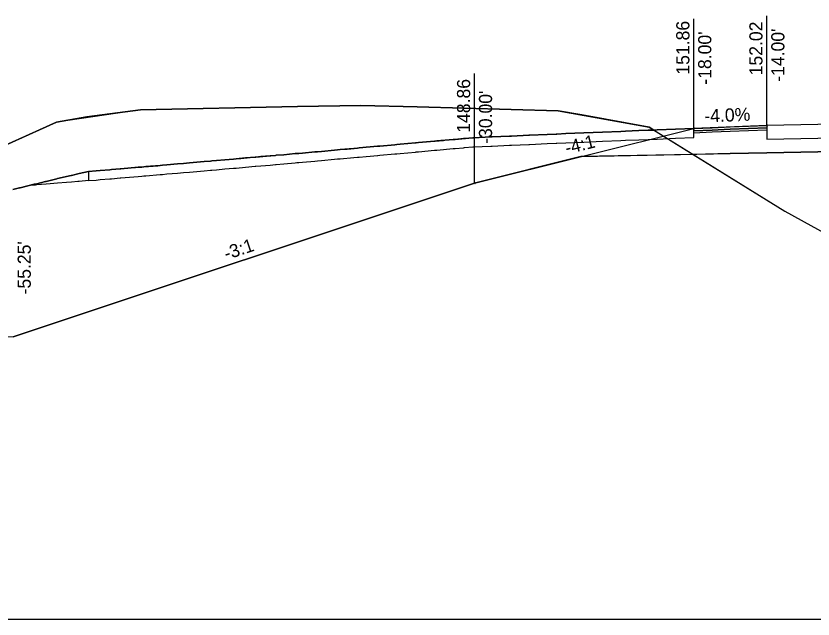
# Model space of a CAD drawing. Extents: x -26 to 4403, y -13 to 9578.
# Drawn here: x 3194.9 to 3238.53, y 8500 to 8533.02 of the extents above; entities that cross this region are included whole.
import ezdxf

# ---------------------------------------------------------------- set-up
doc = ezdxf.new("R2010")
doc.units = 0
for name, color, linetype in [('1', 7, 'Continuous'), ('CONST_LV3', 7, 'Continuous'), ('CONST_PROF_LV1', 7, 'Continuous'), ('Default', 7, 'Continuous'), ('DTM CONTOURS_MAJOR', 7, 'Continuous'), ('DTM_P_FINISHED_GRADE', 7, 'Continuous'), ('DTM_X_BOUNDARY', 7, 'Continuous'), ('DTM_X_GROUND', 7, 'Continuous'), ('XS_CELL', 7, 'Continuous'), ('XS_M_SHAPES_EARTHWORK', 7, 'Continuous'), ('XS_P_ASPHALT', 7, 'Continuous'), ('XS_P_DR_ASPHALT', 7, 'Continuous'), ('XS_P_DR_ASPHALT_B', 7, 'Continuous'), ('XS_P_DR_GRAVEL', 7, 'Continuous'), ('XS_P_GROUND', 7, 'Continuous'), ('XS_P_SHOULDER', 7, 'Continuous'), ('XS_P_SUBGRADE_GRANULAR', 7, 'Continuous'), ('XS_P_TX_CLEARZONE', 7, 'Continuous'), ('XS_P_TX_FS_BS', 7, 'Continuous')]:
    doc.layers.add(name, color=color, linetype=linetype)

msp = doc.modelspace()

# ---------------------------------------------------------------- linework, layer by layer
at = {"layer": '1'}
for p, q in [((3201.713, 8527.882), (3197.118, 8527.209)), ((3224.572, 8527.826), (3229.562, 8526.928))]:
    msp.add_line(p, q, dxfattribs=at)
at = {"layer": 'CONST_LV3'}
for points in [[(3198.868, 8524.501), (3199.286, 8524.536), (3199.509, 8524.555), (3200.037, 8524.599), (3200.124, 8524.607), (3200.607, 8524.647), (3200.649, 8524.651), (3200.714, 8524.657), (3201.69, 8524.738), (3201.788, 8524.748), (3201.898, 8524.757), (3202.667, 8524.821), (3202.927, 8524.845), (3203.163, 8524.865), (3203.737, 8524.913), (3204.066, 8524.944), (3204.403, 8524.972), (3204.809, 8525.006), (3205.203, 8525.043), (3205.553, 8525.072), (3205.619, 8525.077), (3205.882, 8525.099), (3206.339, 8525.142), (3206.813, 8525.182), (3206.956, 8525.193), (3207.208, 8525.217), (3207.721, 8525.26), (3207.987, 8525.285), (3208.031, 8525.288), (3208.605, 8525.342), (3209.105, 8525.384), (3209.143, 8525.387), (3209.56, 8525.421), (3210.18, 8525.479), (3210.28, 8525.487), (3210.388, 8525.496), (3210.587, 8525.513), (3211.254, 8525.575), (3211.402, 8525.587), (3211.616, 8525.605), (3212.327, 8525.671), (3212.508, 8525.686), (3212.646, 8525.697), (3213.015, 8525.732), (3213.224, 8525.749), (3213.6, 8525.784), (3213.677, 8525.79), (3214.468, 8525.863), (3214.68, 8525.88), (3214.709, 8525.883), (3214.823, 8525.892), (3215.64, 8525.967), (3215.741, 8525.976), (3215.748, 8525.976), (3215.934, 8525.991), (3216.773, 8526.068), (3216.806, 8526.071), (3216.936, 8526.081), (3217.804, 8526.161), (3217.854, 8526.165), (3218.302, 8526.206), (3218.382, 8526.212), (3218.835, 8526.253), (3218.893, 8526.258), (3218.945, 8526.262), (3219.864, 8526.345), (3219.908, 8526.349), (3219.924, 8526.35), (3219.952, 8526.351), (3220.891, 8526.394), (3220.949, 8526.397), (3220.959, 8526.397), (3221.917, 8526.44), (3221.967, 8526.442), (3222.016, 8526.444), (3222.975, 8526.487), (3222.981, 8526.487), (3223.469, 8526.508), (3223.491, 8526.509), (3223.98, 8526.53), (3224.974, 8526.573), (3224.996, 8526.574), (3225.991, 8526.616), (3226.995, 8526.657), (3226.998, 8526.657), (3228, 8526.698), (3228.259, 8526.708), (3229, 8526.738), (3230, 8526.778), (3231, 8526.818), (3232, 8526.858), (3233, 8526.898), (3234, 8526.938), (3235, 8526.978), (3236, 8527.018)], [(3220, 8523.858), (3220, 8523.858), (3225.826, 8525.314)]]:
    msp.add_lwpolyline(points, dxfattribs=at)
at = {"layer": 'DTM_P_FINISHED_GRADE'}
for points in [[(3198.868, 8524.501), (3199.286, 8524.536), (3199.509, 8524.555), (3200.037, 8524.599), (3200.124, 8524.607), (3200.607, 8524.647), (3200.649, 8524.651), (3201.598, 8524.73), (3201.788, 8524.748), (3201.898, 8524.757), (3202.006, 8524.767), (3202.793, 8524.833), (3202.927, 8524.845), (3203.163, 8524.865), (3203.737, 8524.913), (3204.066, 8524.944), (3204.403, 8524.972), (3204.809, 8525.006), (3205.203, 8525.043), (3205.553, 8525.072), (3205.619, 8525.077), (3205.882, 8525.099), (3206.339, 8525.142), (3206.813, 8525.182), (3206.956, 8525.193), (3207.473, 8525.242), (3207.987, 8525.285), (3208.031, 8525.288), (3208.311, 8525.315), (3208.813, 8525.356), (3209.105, 8525.384), (3209.143, 8525.387), (3209.56, 8525.421), (3210.18, 8525.479), (3210.28, 8525.487), (3210.388, 8525.496), (3210.587, 8525.513), (3211.254, 8525.575), (3211.402, 8525.587), (3211.616, 8525.605), (3212.327, 8525.671), (3212.508, 8525.686), (3212.646, 8525.697), (3213.398, 8525.767), (3213.6, 8525.784), (3213.677, 8525.79), (3214.065, 8525.826), (3214.286, 8525.844), (3214.68, 8525.88), (3214.709, 8525.883), (3214.823, 8525.892), (3215.639, 8525.967), (3215.741, 8525.976), (3215.748, 8525.976), (3215.934, 8525.991), (3216.773, 8526.068), (3216.806, 8526.071), (3216.936, 8526.081), (3217.804, 8526.161), (3217.854, 8526.165), (3217.94, 8526.172), (3218.835, 8526.253), (3218.893, 8526.258), (3218.945, 8526.262), (3219.4, 8526.303), (3219.449, 8526.307), (3219.908, 8526.349), (3219.924, 8526.35), (3219.952, 8526.351), (3220.891, 8526.394), (3220.949, 8526.397), (3220.959, 8526.397), (3221.917, 8526.44), (3221.967, 8526.442), (3222.016, 8526.444), (3222.975, 8526.487), (3222.981, 8526.487), (3223.007, 8526.488), (3223.98, 8526.53), (3224.475, 8526.552), (3224.503, 8526.553), (3224.996, 8526.574), (3225.991, 8526.616), (3226.995, 8526.657), (3226.998, 8526.657), (3228, 8526.698), (3228.001, 8526.698), (3228.259, 8526.708), (3229, 8526.738), (3230, 8526.778), (3231, 8526.818), (3232, 8526.858)], [(3232, 8526.858), (3233, 8526.898), (3234, 8526.938), (3235, 8526.978), (3236, 8527.018)]]:
    msp.add_lwpolyline(points, dxfattribs=at)
at = {"layer": 'DTM_X_GROUND'}
msp.add_lwpolyline([(3153.808, 8513.95), (3170.909, 8514.966), (3177.153, 8518.209), (3197.118, 8527.209), (3198.789, 8527.5), (3201.713, 8527.882), (3210.312, 8528.066), (3213.777, 8528.123), (3216.864, 8528.039), (3224.572, 8527.826), (3225.877, 8527.605), (3229.562, 8526.928), (3236.992, 8522.323), (3249.998, 8515.154), (3250, 8515.153), (3250.751, 8515.018), (3252.885, 8514.328), (3255.752, 8514.055), (3262.783, 8513.146), (3270.679, 8512.757), (3325.754, 8511.013), (3363.759, 8510.776), (3378.096, 8510.765), (3400, 8511.068)], dxfattribs=at)
at = {"layer": 'XS_CELL'}
msp.add_line((3000, 8500), (3250, 8500), dxfattribs=at)
at = {"layer": 'XS_M_SHAPES_EARTHWORK'}
for points in [[(3170.909, 8514.966), (3177.153, 8518.209), (3197.118, 8527.209), (3198.789, 8527.5), (3201.713, 8527.882), (3210.312, 8528.066), (3213.777, 8528.123), (3216.864, 8528.039), (3224.572, 8527.826), (3225.877, 8527.605), (3229.562, 8526.928), (3231.967, 8525.437), (3225.826, 8525.314), (3220, 8523.858), (3194.753, 8515.443)], [(3231.967, 8525.437), (3236.992, 8522.323), (3249.998, 8515.154), (3250, 8515.153), (3250.751, 8515.018), (3252.885, 8514.328), (3255.752, 8514.055), (3262.783, 8513.146), (3270.679, 8512.757), (3317.781, 8511.266), (3280, 8523.858), (3274.174, 8525.314), (3266, 8525.478), (3264, 8525.518), (3250, 8525.798), (3236, 8525.518), (3234, 8525.478)]]:
    msp.add_lwpolyline(points, close=True, dxfattribs=at)
at = {"layer": 'XS_P_ASPHALT'}
msp.add_lwpolyline([(3236, 8527.018), (3236, 8527.018), (3236, 8526.268), (3236, 8526.268), (3236, 8526.268), (3250, 8526.548), (3264, 8526.268), (3264, 8526.268), (3264, 8526.268), (3264, 8527.018), (3264, 8527.018), (3250, 8527.298), (3236, 8527.018)], dxfattribs=at)
at = {"layer": 'XS_P_DR_ASPHALT'}
msp.add_lwpolyline([(3233, 8526.898), (3234, 8526.938), (3234, 8526.938), (3234, 8526.938), (3235, 8526.978), (3235, 8526.978), (3235, 8526.978), (3235, 8526.978), (3236, 8527.018), (3236, 8526.893), (3235, 8526.853), (3235, 8526.853), (3235, 8526.853), (3235, 8526.853), (3234, 8526.813), (3234, 8526.813), (3234, 8526.813), (3233, 8526.773), (3233, 8526.773), (3233, 8526.773), (3232, 8526.733), (3232, 8526.858), (3233, 8526.898), (3233, 8526.898), (3233, 8526.898)], dxfattribs=at)
at = {"layer": 'XS_P_DR_ASPHALT_B'}
msp.add_lwpolyline([(3233, 8526.773), (3234, 8526.813), (3234, 8526.813), (3234, 8526.813), (3235, 8526.853), (3235, 8526.853), (3235, 8526.853), (3235, 8526.853), (3236, 8526.893), (3236, 8526.768), (3235, 8526.728), (3235, 8526.728), (3235, 8526.728), (3235, 8526.728), (3234, 8526.688), (3234, 8526.688), (3234, 8526.688), (3233, 8526.648), (3233, 8526.648), (3233, 8526.648), (3232, 8526.608), (3232, 8526.733), (3233, 8526.773), (3233, 8526.773), (3233, 8526.773)], dxfattribs=at)
at = {"layer": 'XS_P_DR_GRAVEL'}
for points in [[(3200.037, 8524.599), (3199.509, 8524.555), (3199.286, 8524.536), (3198.868, 8524.501), (3198.868, 8524.001), (3199.286, 8524.036), (3199.509, 8524.055), (3200.037, 8524.099), (3200.124, 8524.107), (3200.607, 8524.147), (3200.649, 8524.151), (3201.598, 8524.23), (3201.788, 8524.248), (3201.898, 8524.257), (3202.006, 8524.267), (3202.793, 8524.333), (3202.927, 8524.345), (3203.163, 8524.365), (3203.737, 8524.413), (3204.066, 8524.444), (3204.403, 8524.472), (3204.809, 8524.506), (3205.203, 8524.543), (3205.553, 8524.572), (3205.619, 8524.577), (3205.882, 8524.599), (3206.339, 8524.642), (3206.813, 8524.682), (3206.956, 8524.693), (3207.473, 8524.742), (3207.987, 8524.785), (3208.031, 8524.788), (3208.311, 8524.815), (3208.813, 8524.856), (3209.105, 8524.884), (3209.143, 8524.887), (3209.56, 8524.921), (3210.18, 8524.979), (3210.28, 8524.987), (3210.388, 8524.996), (3210.587, 8525.013), (3211.254, 8525.075), (3211.402, 8525.087), (3211.616, 8525.105), (3212.327, 8525.171), (3212.508, 8525.186), (3212.646, 8525.197), (3213.398, 8525.267), (3213.6, 8525.284), (3213.677, 8525.29), (3214.065, 8525.326), (3214.286, 8525.344), (3214.68, 8525.38), (3214.709, 8525.383), (3214.823, 8525.392), (3215.639, 8525.467), (3215.741, 8525.476), (3215.748, 8525.476), (3215.934, 8525.491), (3216.773, 8525.568), (3216.806, 8525.571), (3216.936, 8525.581), (3217.804, 8525.661), (3217.854, 8525.665), (3217.94, 8525.672), (3218.835, 8525.753), (3218.893, 8525.758), (3218.945, 8525.762), (3219.4, 8525.803), (3219.449, 8525.807), (3219.908, 8525.849), (3219.924, 8525.85), (3219.952, 8525.851), (3220.891, 8525.894), (3220.949, 8525.897), (3220.959, 8525.897), (3221.917, 8525.94), (3221.967, 8525.942), (3222.016, 8525.944), (3222.975, 8525.987), (3222.981, 8525.987), (3223.007, 8525.988), (3223.98, 8526.03), (3224.475, 8526.052), (3224.503, 8526.053), (3224.996, 8526.074), (3225.991, 8526.116), (3226.995, 8526.157), (3226.998, 8526.157), (3228, 8526.198), (3228.001, 8526.198), (3228.259, 8526.208), (3228.259, 8526.208), (3229, 8526.238), (3230, 8526.278), (3230, 8526.278), (3231, 8526.318), (3231, 8526.318), (3231, 8526.318), (3232, 8526.358), (3232, 8526.358), (3232, 8526.858), (3232, 8526.858), (3231, 8526.818), (3231, 8526.818), (3231, 8526.818), (3230, 8526.778), (3230, 8526.778), (3229, 8526.738), (3228.259, 8526.708), (3228.259, 8526.708), (3228.001, 8526.698), (3228, 8526.698), (3226.998, 8526.657), (3226.995, 8526.657), (3225.991, 8526.616), (3224.996, 8526.574), (3224.503, 8526.553), (3224.475, 8526.552), (3223.98, 8526.53), (3223.007, 8526.488), (3222.981, 8526.487), (3222.975, 8526.487), (3222.016, 8526.444), (3221.967, 8526.442), (3221.917, 8526.44), (3220.959, 8526.397), (3220.949, 8526.397), (3220.891, 8526.394), (3219.952, 8526.351), (3219.924, 8526.35), (3219.908, 8526.349), (3219.449, 8526.307), (3219.4, 8526.303), (3218.945, 8526.262), (3218.893, 8526.258), (3218.835, 8526.253), (3217.94, 8526.172), (3217.854, 8526.165), (3217.804, 8526.161), (3216.936, 8526.081), (3216.806, 8526.071), (3216.773, 8526.068), (3215.934, 8525.991), (3215.748, 8525.976), (3215.741, 8525.976), (3215.639, 8525.967), (3214.823, 8525.892), (3214.709, 8525.883), (3214.68, 8525.88), (3214.286, 8525.844), (3214.065, 8525.826), (3213.677, 8525.79), (3213.6, 8525.784), (3213.398, 8525.767), (3212.646, 8525.697), (3212.508, 8525.686), (3212.327, 8525.671), (3211.616, 8525.605), (3211.402, 8525.587), (3211.254, 8525.575), (3210.587, 8525.513), (3210.388, 8525.496), (3210.28, 8525.487), (3210.18, 8525.479), (3209.56, 8525.421), (3209.143, 8525.387), (3209.105, 8525.384), (3208.813, 8525.356), (3208.311, 8525.315), (3208.031, 8525.288), (3207.987, 8525.285), (3207.473, 8525.242), (3206.956, 8525.193), (3206.813, 8525.182), (3206.339, 8525.142), (3205.882, 8525.099), (3205.619, 8525.077), (3205.553, 8525.072), (3205.203, 8525.043), (3204.809, 8525.006), (3204.403, 8524.972), (3204.066, 8524.944), (3203.737, 8524.913), (3203.163, 8524.865), (3202.927, 8524.845), (3202.793, 8524.833), (3202.006, 8524.767), (3201.898, 8524.757), (3201.788, 8524.748), (3201.598, 8524.73), (3200.649, 8524.651), (3200.607, 8524.647), (3200.124, 8524.607), (3200.037, 8524.599)], [(3198.868, 8524.001), (3198.359, 8523.959), (3198.286, 8523.953), (3197.934, 8523.924), (3197.661, 8523.901), (3197.176, 8523.861), (3196.778, 8523.829), (3196.549, 8523.81), (3196.043, 8523.768), (3195.968, 8523.762), (3195.899, 8523.756), (3195.632, 8523.735)]]:
    msp.add_lwpolyline(points, dxfattribs=at)
at = {"layer": 'XS_P_GROUND'}
for p, q in [((3228, 8526.698), (3228.259, 8526.708)), ((3228.259, 8526.708), (3229, 8526.738)), ((3229, 8526.738), (3229.815, 8526.77)), ((3218.945, 8526.262), (3219.4, 8526.303)), ((3219.4, 8526.303), (3219.407, 8526.304)), ((3220.891, 8526.394), (3220.949, 8526.397)), ((3220.949, 8526.397), (3220.959, 8526.397)), ((3223.98, 8526.53), (3224.475, 8526.552)), ((3224.475, 8526.552), (3224.503, 8526.553)), ((3215.934, 8525.991), (3216.773, 8526.068)), ((3216.773, 8526.068), (3216.806, 8526.071)), ((3216.806, 8526.071), (3216.936, 8526.081)), ((3216.936, 8526.081), (3217.804, 8526.161)), ((3217.804, 8526.161), (3217.854, 8526.165)), ((3210.18, 8525.479), (3210.28, 8525.487)), ((3211.402, 8525.587), (3211.616, 8525.605)), ((3211.616, 8525.605), (3212.327, 8525.671)), ((3213.398, 8525.767), (3213.6, 8525.784)), ((3213.6, 8525.784), (3213.677, 8525.79)), ((3204.809, 8525.006), (3205.203, 8525.043)), ((3205.203, 8525.043), (3205.553, 8525.072)), ((3206.339, 8525.142), (3206.813, 8525.182)), ((3206.813, 8525.182), (3206.956, 8525.193)), ((3198.868, 8524.501), (3199.286, 8524.536)), ((3199.286, 8524.536), (3199.509, 8524.555)), ((3200.124, 8524.607), (3200.607, 8524.647)), ((3201.788, 8524.748), (3201.898, 8524.757)), ((3201.898, 8524.757), (3202.006, 8524.767)), ((3202.006, 8524.767), (3202.667, 8524.822)), ((3202.667, 8524.822), (3202.793, 8524.833)), ((3202.793, 8524.833), (3202.927, 8524.845)), ((3203.737, 8524.913), (3204.066, 8524.944))]:
    msp.add_line(p, q, dxfattribs=at)
for points in [[(3229.815, 8526.77), (3229.562, 8526.928), (3225.877, 8527.605), (3224.572, 8527.826), (3216.864, 8528.039), (3213.777, 8528.123), (3210.312, 8528.066), (3201.713, 8527.882), (3198.789, 8527.5), (3197.118, 8527.209), (3180.966, 8519.928)], [(3194.753, 8515.443), (3220, 8523.858), (3220, 8523.858), (3220, 8523.858), (3232, 8526.858)], [(3219.407, 8526.304), (3219.449, 8526.308), (3219.864, 8526.345), (3219.908, 8526.349)], [(3219.908, 8526.349), (3219.924, 8526.35), (3219.952, 8526.351), (3220.891, 8526.394)], [(3220.959, 8526.397), (3221.917, 8526.44), (3221.967, 8526.442)], [(3221.967, 8526.442), (3222.016, 8526.444), (3222.975, 8526.487)], [(3222.975, 8526.487), (3223.007, 8526.488), (3223.469, 8526.508), (3223.491, 8526.509), (3223.98, 8526.53)], [(3224.503, 8526.553), (3224.974, 8526.573), (3224.996, 8526.574), (3225.991, 8526.616)], [(3225.991, 8526.616), (3226.995, 8526.657), (3228, 8526.698)], [(3214.072, 8525.826), (3214.286, 8525.846), (3214.468, 8525.863), (3214.68, 8525.88), (3214.709, 8525.883), (3214.823, 8525.892), (3215.639, 8525.967)], [(3215.639, 8525.967), (3215.741, 8525.976), (3215.934, 8525.991)], [(3217.854, 8526.165), (3217.94, 8526.173), (3218.302, 8526.206), (3218.382, 8526.212), (3218.835, 8526.253)], [(3218.835, 8526.253), (3218.893, 8526.258), (3218.945, 8526.262)], [(3209.143, 8525.387), (3209.56, 8525.421), (3210.18, 8525.479)], [(3210.28, 8525.487), (3210.388, 8525.496), (3210.587, 8525.513), (3211.254, 8525.575), (3211.402, 8525.587)], [(3212.327, 8525.671), (3212.508, 8525.686), (3212.646, 8525.697)], [(3212.646, 8525.697), (3213.015, 8525.732), (3213.021, 8525.732)], [(3213.021, 8525.732), (3213.223, 8525.751), (3213.398, 8525.767)], [(3213.677, 8525.79), (3214.065, 8525.826), (3214.072, 8525.826)], [(3204.066, 8524.944), (3204.403, 8524.972), (3204.809, 8525.006)], [(3205.553, 8525.072), (3205.619, 8525.077), (3205.882, 8525.099), (3206.339, 8525.142)], [(3206.956, 8525.193), (3207.208, 8525.217), (3207.212, 8525.217)], [(3207.212, 8525.217), (3207.473, 8525.242), (3207.721, 8525.263)], [(3207.721, 8525.263), (3207.987, 8525.285), (3208.031, 8525.288), (3208.311, 8525.315), (3208.315, 8525.315)], [(3208.315, 8525.315), (3208.605, 8525.342), (3208.813, 8525.359), (3209.105, 8525.384), (3209.143, 8525.387)], [(3199.509, 8524.555), (3200.037, 8524.599), (3200.124, 8524.607)], [(3200.607, 8524.647), (3200.649, 8524.651), (3200.714, 8524.657), (3201.598, 8524.731), (3201.69, 8524.738), (3201.788, 8524.748)], [(3202.927, 8524.845), (3203.163, 8524.865), (3203.737, 8524.913)], [(3198.868, 8524.501), (3198.359, 8524.387), (3198.353, 8524.385), (3197.934, 8524.289), (3197.915, 8524.283), (3197.176, 8524.111), (3197.147, 8524.101), (3196.549, 8523.959), (3196.512, 8523.947), (3195.968, 8523.816), (3195.9, 8523.8), (3195.129, 8523.613), (3195.088, 8523.603), (3194.732, 8523.516)], [(3194.732, 8523.516), (3195.088, 8523.603), (3195.129, 8523.613), (3195.632, 8523.735), (3195.9, 8523.8), (3195.968, 8523.816), (3196.512, 8523.947), (3196.549, 8523.959), (3197.147, 8524.101), (3197.176, 8524.111), (3197.915, 8524.283), (3197.934, 8524.289), (3198.359, 8524.387), (3198.868, 8524.501)]]:
    msp.add_lwpolyline(points, dxfattribs=at)
at = {"layer": 'XS_P_SHOULDER'}
msp.add_lwpolyline([(3236, 8527.018), (3232, 8526.858)], dxfattribs=at)
at = {"layer": 'XS_P_SUBGRADE_GRANULAR'}
for points in [[(3225.826, 8525.314), (3225.826, 8525.314), (3234, 8525.478), (3234, 8525.478), (3236, 8525.518)], [(3236, 8525.518), (3236, 8525.518), (3250, 8525.798)]]:
    msp.add_lwpolyline(points, dxfattribs=at)
at = {"layer": 'XS_P_TX_CLEARZONE'}
for p, q in [((3232, 8526.858), (3232, 8532.858)), ((3232, 8526.858), (3232, 8532.858)), ((3232, 8526.858), (3232, 8532.858)), ((3236, 8527.018), (3236, 8533.018)), ((3236, 8527.018), (3236, 8533.018)), ((3236, 8527.018), (3236, 8533.018)), ((3236, 8527.018), (3236, 8533.018)), ((3236, 8527.018), (3236, 8533.018)), ((3236, 8527.018), (3236, 8533.018)), ((3220, 8523.858), (3220, 8529.858)), ((3220, 8523.858), (3220, 8529.858)), ((3220, 8523.858), (3220, 8529.858)), ((3220, 8523.858), (3220, 8529.858)), ((3220, 8523.858), (3220, 8529.858)), ((3220, 8523.858), (3220, 8529.858))]:
    msp.add_line(p, q, dxfattribs=at)

# ---------------------------------------------------------------- texts
at = {"layer": 'CONST_PROF_LV1'}
msp.add_text('X', height=0.12, dxfattribs=at).set_placement((3219.961, 8523.798))
at = {"layer": 'Default'}
msp.add_text('X', height=0.12, dxfattribs=at).set_placement((3219.961, 8523.798))
at = {"layer": 'DTM CONTOURS_MAJOR'}
msp.add_text('X', height=0.12, dxfattribs=at).set_placement((3235.961, 8526.958))
at = {"layer": 'DTM_X_BOUNDARY'}
msp.add_text('X', height=0.12, dxfattribs=at).set_placement((3231.961, 8526.798))
at = {"layer": 'XS_P_TX_CLEARZONE'}
for s, p in [('151.86', (3231.76, 8529.804)), ('151.86', (3231.76, 8529.804)), ('151.86', (3231.76, 8529.804)), ('152.02', (3235.76, 8529.765)), ('152.02', (3235.76, 8529.765)), ('152.02', (3235.76, 8529.765)), ('152.02', (3235.76, 8529.765)), ('152.02', (3235.76, 8529.765)), ('152.02', (3235.76, 8529.765)), ("-18.00'", (3232.96, 8529.254)), ("-18.00'", (3232.96, 8529.254)), ("-18.00'", (3232.96, 8529.254)), ("-14.00'", (3236.96, 8529.414)), ("-14.00'", (3236.96, 8529.414)), ("-14.00'", (3236.96, 8529.414)), ("-14.00'", (3236.96, 8529.414)), ("-14.00'", (3236.96, 8529.414)), ("-14.00'", (3236.96, 8529.414)), ('148.86', (3219.76, 8526.622)), ('148.86', (3219.76, 8526.622)), ('148.86', (3219.76, 8526.622)), ('148.86', (3219.76, 8526.622)), ('148.86', (3219.76, 8526.622)), ('148.86', (3219.76, 8526.622)), ("-30.00'", (3220.96, 8526.016)), ("-30.00'", (3220.96, 8526.016)), ("-30.00'", (3220.96, 8526.016)), ("-30.00'", (3220.96, 8526.016)), ("-30.00'", (3220.96, 8526.016)), ("-30.00'", (3220.96, 8526.016)), ("-55.25'", (3195.713, 8517.771)), ("-55.25'", (3195.713, 8517.771)), ("-55.25'", (3195.713, 8517.771)), ("-55.25'", (3195.713, 8517.771)), ("-55.25'", (3195.713, 8517.771)), ("-55.25'", (3195.713, 8517.771))]:
    msp.add_text(s, height=0.72, rotation=90, dxfattribs=at).set_placement(p)
at = {"layer": 'XS_P_TX_FS_BS'}
for s, rotation, p in [('-4.0%', 2.2906, (3232.592, 8527.182)), ('-4.0%', 2.2906, (3232.592, 8527.182)), ('-4.0%', 2.2906, (3232.592, 8527.182)), ('-4:1', 14.0362, (3225.047, 8525.429)), ('-4:1', 14.0362, (3225.047, 8525.429)), ('-4:1', 14.0362, (3225.047, 8525.429)), ('-3:1', 18.4332, (3206.421, 8519.648)), ('-3:1', 18.4332, (3206.421, 8519.648)), ('-3:1', 18.4332, (3206.421, 8519.648))]:
    msp.add_text(s, height=0.72, rotation=rotation, dxfattribs=at).set_placement(p)

doc.saveas('drawing.dxf')
